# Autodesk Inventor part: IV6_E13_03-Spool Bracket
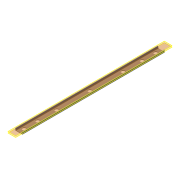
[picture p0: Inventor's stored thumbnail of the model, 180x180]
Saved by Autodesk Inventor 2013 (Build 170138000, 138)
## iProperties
Shininess: 64.0
Length Units: 11269
Angle Units: 11279
Time Units: 11290
Mass Units: 11286
Length Display Precision: 3
Angle Display Precision: 2
Compacted: True
Created: 2002-08
Part Number: IV6_E13_03-Spool Bracket
Document SubType Name: Modeling
Designer: kalamea
Density: 1 g/cm^3
Material: Generic
Mass: 126.038 g
Surface Area: 860.848 cm^2
Volume: 126.038 cm^3
Density: 0.0
Volumn: 0.0
Area: 0.0
PropertySet Name: Model Information
Control State: 0
Master: False
Checked Out: False
DRAWING NUMBER: ME10-2007-PT
d0: 38.100 mm
d1: 12.700 mm
d2: 10.160 mm
d3: 2.540 mm
d4: 2.540 mm
d5: 5.080 mm
d6: 5.080 mm
d7: 762.000 mm
d8: 0.00 deg
d9: 28.575 mm
d10: 101.600 mm
d11: 203.200 mm
d12: 381.000 mm
d13: 19.050 mm
d20: -381.000 mm
Author: kalamea
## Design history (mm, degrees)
sketch "Sketch1"
  geometry: L1 (-13.64, -13.56)-(24.46, -13.56); L2 (24.46, -13.56)-(24.46, -0.86); L3 (24.46, -0.86)-(21.92, -0.86) reference; L4 (21.92, -0.86)-(19.38, -11.02); L5 (19.38, -11.02)-(-8.56, -11.02); L6 (-8.56, -11.02)-(-11.1, -1.421); L7 (-11.1, -1.421)-(-13.64, -1.421); L8 (-13.64, -1.421)-(-13.64, -13.56)
  constraints: 16 end point, 4 parallel, 2 horizontal, 1 perpendicular, 1 other
  dimensions: "d0" = 38.1 distance of L1.start L1.end; "d1" = 12.7 distance of L1.end L2.end; "d2" = 10.16 vertical distance of L4.end L2.end; "d3" = 2.54 distance of L2.end L3.end; "d4" = 2.54 distance of L6.end L7.end; "d5" = 5.08 horizontal distance of L5.end L7.end; "d6" = 5.08 horizontal distance of L2.end L4.end
extrude "Extrusion1" new body sketch "Sketch1" distance "d7" = 762; taper "d8" = 0 deg
sketch "Sketch2"
  geometry: L1 (38.1, 762)-(0, 762) reference; L2 (0, 0)-(0, 762) reference; L3 (19.05, 381)-(19.05, 762); 3 further points
  constraints: 3 point on line, 2 end point, 1 midpoint, 1 parallel, 1 vertical
  dimensions: "d9" = 28.575 distance from line of point (19.05, 733.425) L1; "d10" = 101.6 distance from line of point (19.05, 660.4) L1; "d11" = 203.2 distance from line of point (19.05, 558.8) L1; "d12" = 381 distance from line of L3.start L1
hole "Hole1" sketch "Sketch2" at (19.05, 733.425), (19.05, 660.4), (19.05, 558.8), (19.05, 381) diameter "d13" = 19.05; stored, may be unused: countersink angle "d17" = 82 deg, drill point angle "d19" = 118 deg; dims "d14" = 12.7, "d15" = 9.525, "d16" = 6.35, "d18" = 19.05
workplane "Work Plane1"
mirror "Mirror1"
workplane "Work Plane2"
body "Solid1"
other parameters: "d20" = -381
